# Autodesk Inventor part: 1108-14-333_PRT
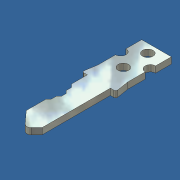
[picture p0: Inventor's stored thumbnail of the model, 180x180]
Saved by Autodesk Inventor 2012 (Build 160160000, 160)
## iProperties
Created: 2007-03
Part Number: 1108-14-333_PRT
Document SubType Name: Modeling
Designer: Andy Moles
Density: 1 g/cm^3
Mass: 0.443583 g
Surface Area: 6.97725 cm^2
Volume: 0.443583 cm^3
Material: Default
Author: Andy Moles
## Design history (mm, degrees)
feature "Base1"
body "Solid1"
